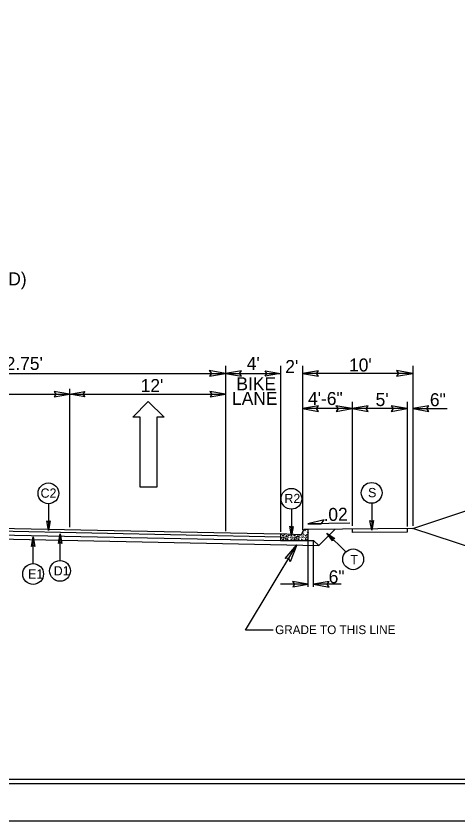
# Model space of a CAD drawing. Extents: x 957297 to 961629, y 830661 to 840840.
# Drawn here: x 959624.2 to 959889, y 837206.3 to 837689.4 of the extents above; entities that cross this region are included whole.
import ezdxf

# ---------------------------------------------------------------- set-up
doc = ezdxf.new("R2010")
doc.units = 0
for name, color, linetype in [('Old_Level_1', 7, 'Continuous'), ('Old_Level_11', 7, 'Continuous'), ('Old_Level_3', 7, 'Continuous'), ('Prop Dimension Text', 7, 'Continuous'), ('Prop Lane Arrow CELL', 7, 'Continuous'), ('Sheet Plot Border Inside CELL', 7, 'Continuous'), ('Sheet Plot Border Outside CELL', 7, 'Continuous'), ('Sheet Typical CELL', 7, 'Continuous'), ('Typical ID Circle CELL', 7, 'Continuous'), ('Typical Terminator CELL', 7, 'Continuous'), ('Typical Text ID Circle CELL', 7, 'Continuous')]:
    doc.layers.add(name, color=color, linetype=linetype)

# ---------------------------------------------------------------- blocks, each defined once
blk = doc.blocks.new('Lane Arrow Through')
at = {"layer": 'Prop Lane Arrow CELL'}
for p, q in [((-3.15, 1.6), (-3.15, 3.1)), ((-3.15, 3.1), (0, 0)), ((-17.15, 1.6), (-3.15, 1.6)), ((-17.15, -1.7), (-17.15, 1.6)), ((0, 0), (-3.15, -3.2)), ((-3.15, -1.7), (-17.15, -1.7)), ((-3.15, -3.2), (-3.15, -1.7))]:
    blk.add_line(p, q, dxfattribs=at)

msp = doc.modelspace()

# ---------------------------------------------------------------- linework, layer by layer
at = {"layer": 'Old_Level_1'}
for p, q in [((959749.66, 837479.5), (959749.66, 837380.2)), ((959782.66, 837479.5), (959782.66, 837379.7)), ((959795.87, 837479.5), (959795.87, 837380.9)), ((959861.91, 837479.5), (959861.91, 837383.36)), ((959494.54, 837474.88), (959749.66, 837474.88)), ((959749.66, 837474.88), (959782.66, 837474.88)), ((959861.91, 837474.88), (959795.87, 837474.88)), ((959562.7, 837462.34), (959656.18, 837462.34)), ((959656.18, 837465.69), (959656.18, 837382.66)), ((959656.18, 837462.34), (959749.66, 837462.34)), ((959825.59, 837457.89), (959825.59, 837383.36)), ((959858.61, 837457.89), (959858.61, 837382.99)), ((959825.59, 837453.73), (959795.87, 837453.73)), ((959858.61, 837453.73), (959825.59, 837453.73)), ((959861.91, 837453.73), (959882.58, 837453.73)), ((959861.91, 837381.88), (959939.1, 837407.61)), ((959824.16, 837385.02), (959799.05, 837384.52)), ((959562.67, 837381.32), (959782.66, 837376.87)), ((959562.7, 837383.05), (959782.66, 837378.6)), ((959861.91, 837381.88), (959798.95, 837381.25)), ((959805.6, 837371.49), (959815.53, 837381.42)), ((959825.59, 837381.52), (959825.59, 837379.34)), ((959858.61, 837381.85), (959858.61, 837379.67)), ((959939.1, 837356.15), (959861.91, 837381.88)), ((959546.62, 837376.89), (959805.61, 837371.66)), ((959562.62, 837379.07), (959782.66, 837374.62)), ((959858.61, 837379.67), (959825.59, 837379.34)), ((959761.73, 837320.85), (959792.43, 837371.92)), ((959799.24, 837374.62), (959802.54, 837374.55)), ((959799.24, 837346.72), (959799.24, 837374.34)), ((959802.54, 837374.55), (959805.6, 837371.49)), ((959802.54, 837346.72), (959802.54, 837374.34)), ((959799.24, 837348.31), (959782.64, 837348.31)), ((959819.14, 837348.31), (959802.54, 837348.31)), ((959778.35, 837320.85), (959761.73, 837320.85))]:
    msp.add_line(p, q, dxfattribs=at)
at = {"layer": 'Old_Level_11'}
for p, q in [((959808.79, 837386.93), (959799.05, 837384.52)), ((959807.06, 837384.68), (959808.79, 837386.93)), ((959799.05, 837384.52), (959807.06, 837384.68))]:
    msp.add_line(p, q, dxfattribs=at)
for points in [[(959740.05, 837473.22), (959749.66, 837474.88), (959740, 837476.59), (959741.22, 837474.88)], [(959759.27, 837476.53), (959749.66, 837474.88), (959759.33, 837473.16), (959758.1, 837474.88)], [(959805.48, 837476.53), (959795.87, 837474.88), (959805.54, 837473.16), (959804.31, 837474.88)], [(959852.3, 837473.22), (959861.91, 837474.88), (959852.25, 837476.59), (959853.47, 837474.88)], [(959805.48, 837455.38), (959795.87, 837453.73), (959805.54, 837452.01), (959804.31, 837453.73)], [(959815.98, 837452.07), (959825.59, 837453.73), (959815.93, 837455.44), (959817.15, 837453.73)], [(959835.2, 837455.38), (959825.59, 837453.73), (959835.26, 837452.01), (959834.03, 837453.73)], [(959849, 837452.07), (959858.61, 837453.73), (959848.95, 837455.44), (959850.17, 837453.73)], [(959871.52, 837455.38), (959861.91, 837453.73), (959871.58, 837452.01), (959870.35, 837453.73)], [(959785.42, 837363.81), (959792.43, 837371.92), (959788.55, 837361.85), (959787.66, 837363.97)]]:
    msp.add_lwpolyline(points, close=True, dxfattribs=at)
at = {"layer": 'Old_Level_3'}
for p, q in [((959798.95, 837381.25), (959797.57, 837381.25)), ((959799.24, 837377.93), (959799.24, 837380.97)), ((959794.2, 837378.02), (959782.66, 837378.6)), ((959782.66, 837378.6), (959782.66, 837374.62)), ((959783.92, 837377.67), (959784.5, 837377.7)), ((959784.5, 837377.12), (959783.92, 837377.67)), ((959784.13, 837375.65), (959783.95, 837375.03)), ((959784.59, 837375), (959784.13, 837375.65)), ((959784.5, 837377.7), (959784.5, 837377.12)), ((959786.18, 837377.06), (959787.02, 837377.3)), ((959786.92, 837376.81), (959786.18, 837377.06)), ((959787.02, 837377.3), (959786.92, 837376.81)), ((959790.65, 837377.67), (959791.23, 837377.7)), ((959791.23, 837377.12), (959790.65, 837377.67)), ((959790.86, 837375.65), (959790.68, 837375.03)), ((959791.32, 837375), (959790.86, 837375.65)), ((959791.23, 837377.7), (959791.23, 837377.12)), ((959792.91, 837377.06), (959793.74, 837377.3)), ((959793.65, 837376.81), (959792.91, 837377.06)), ((959793.74, 837377.3), (959793.65, 837376.81)), ((959794.2, 837378.02), (959794.2, 837378.02)), ((959795.9, 837379.06), (959795.75, 837379.09)), ((959795.79, 837379.21), (959795.9, 837379.06)), ((959797.38, 837377.67), (959797.96, 837377.7)), ((959797.96, 837377.12), (959797.38, 837377.67)), ((959797.58, 837375.65), (959797.41, 837375.03)), ((959798.05, 837375), (959797.58, 837375.65)), ((959797.96, 837377.7), (959797.96, 837377.12)), ((959799.24, 837374.62), (959799.24, 837377.93)), ((959782.66, 837374.62), (959799.24, 837374.62)), ((959783.95, 837375.03), (959784.59, 837375)), ((959786.86, 837375.34), (959786.3, 837374.94)), ((959786.3, 837374.94), (959787.2, 837374.73)), ((959787.2, 837374.73), (959786.86, 837375.34)), ((959790.68, 837375.03), (959791.32, 837375)), ((959793.59, 837375.34), (959793.03, 837374.94)), ((959793.03, 837374.94), (959793.93, 837374.73)), ((959793.93, 837374.73), (959793.59, 837375.34)), ((959797.41, 837375.03), (959798.05, 837375))]:
    msp.add_line(p, q, dxfattribs=at)
for centre in [(959796.3, 837380.41), (959797.4, 837380.53), (959798.26, 837380.16), (959782.87, 837377.21), (959783.15, 837378.32), (959783.21, 837375.74), (959783.36, 837376.29), (959784.16, 837376.63), (959784.41, 837376.08), (959784.93, 837376.53), (959785.08, 837378.13), (959785.52, 837375.86), (959785.63, 837376.93), (959785.81, 837376.05), (959785.91, 837375.53), (959786.34, 837377.52), (959786.86, 837376.05), (959787.51, 837376.32), (959787.78, 837377.67), (959788.46, 837375.43), (959788.86, 837377.27), (959788.89, 837376.47), (959788.98, 837376.2), (959789.6, 837377.21), (959789.94, 837375.74), (959790.09, 837376.29), (959790.89, 837376.63), (959791.14, 837376.08), (959791.66, 837376.53), (959792.24, 837375.86), (959792.36, 837376.93), (959792.54, 837376.05), (959792.63, 837375.53), (959793.07, 837377.52), (959793.59, 837376.05), (959794.23, 837376.32), (959794.51, 837377.67), (959795.19, 837375.43), (959795.5, 837378.29), (959795.59, 837377.27), (959795.62, 837376.47), (959795.71, 837376.2), (959796.26, 837379.12), (959796.33, 837377.21), (959796.6, 837378.32), (959796.66, 837375.74), (959796.82, 837376.29), (959797.25, 837379.61), (959797.62, 837376.63), (959797.86, 837376.08), (959798.39, 837376.53), (959798.42, 837379.43), (959798.54, 837378.13), (959798.97, 837375.86), (959799.09, 837376.93), (959799.18, 837379.52), (959785.08, 837375), (959785.6, 837374.76), (959789.14, 837375.28), (959791.81, 837375), (959792.33, 837374.76), (959795.86, 837375.28), (959798.54, 837375), (959799.06, 837374.76)]:
    msp.add_circle(centre, 0.0432, dxfattribs=at)
for centre, radius, start, end in [((959797.58, 837379.6), 1.66, 90, 178.9266), ((959798.95, 837380.97), 0.287, 0, 90), ((959799.06, 837381.18), 0.0432, 169.6531, 280.3469), ((959788.77, 837378.29), 0.0432, 164.1199, 10.1626), ((959791.81, 837378.13), 0.0432, 162.062, 12.2205), ((959794.28, 837379.66), 1.64, 267.1376, 358.9266), ((959799.27, 837376.05), 0.0432, 150.4173, 209.5827)]:
    msp.add_arc(centre, radius, start, end, dxfattribs=at)
at = {"layer": 'Sheet Plot Border Inside CELL'}
msp.add_lwpolyline([(960390.3, 838283.82), (958723.8, 838283.82), (958723.8, 837228.72), (960390.3, 837228.72)], close=True, dxfattribs=at)
at = {"layer": 'Sheet Plot Border Outside CELL'}
msp.add_lwpolyline([(960394.8, 838306.27), (958710.8, 838306.27), (958710.8, 837206.27), (960394.8, 837206.27)], close=True, dxfattribs=at)
at = {"layer": 'Sheet Typical CELL'}
msp.add_lwpolyline([(960377.8, 838281.27), (958877.8, 838281.27), (958877.8, 837231.27), (960377.8, 837231.27)], close=True, dxfattribs=at)
at = {"layer": 'Typical ID Circle CELL'}
for p, q in [((959643.55, 837396.67), (959643.55, 837380.58)), ((959837.33, 837396.97), (959837.33, 837380.88)), ((959789.22, 837393.42), (959789.22, 837377.33)), ((959634.38, 837360.7), (959634.38, 837376.79)), ((959650.51, 837362.56), (959650.51, 837378.65)), ((959821.83, 837367.71), (959810.46, 837379.09))]:
    msp.add_line(p, q, dxfattribs=at)
for centre in [(959837.33, 837403.19), (959643.55, 837402.89), (959789.22, 837399.64), (959826.23, 837363.31), (959650.51, 837356.34), (959634.38, 837354.48)]:
    msp.add_circle(centre, 6.23, dxfattribs=at)
at = {"layer": 'Typical Terminator CELL'}
for points in [[(959773.44, 837476.47), (959782.66, 837474.88), (959773.39, 837473.24), (959774.57, 837474.88)], [(959646.96, 837460.75), (959656.18, 837462.34), (959646.91, 837463.98), (959648.09, 837462.34)], [(959665.4, 837460.75), (959656.18, 837462.34), (959665.46, 837463.98), (959664.28, 837462.34)], [(959740.44, 837460.75), (959749.66, 837462.34), (959740.39, 837463.98), (959741.57, 837462.34)], [(959644.54, 837386.35), (959643.55, 837380.58), (959642.52, 837386.38), (959643.55, 837385.64)], [(959838.33, 837386.65), (959837.33, 837380.88), (959836.31, 837386.68), (959837.33, 837385.94)], [(959790.22, 837383.09), (959789.22, 837377.33), (959788.2, 837383.13), (959789.22, 837382.39)], [(959633.39, 837371.02), (959634.38, 837376.79), (959635.4, 837370.99), (959634.38, 837371.73)], [(959649.52, 837372.89), (959650.51, 837378.65), (959651.54, 837372.85), (959650.51, 837373.59)], [(959813.83, 837374.31), (959810.46, 837379.09), (959815.28, 837375.71), (959814.03, 837375.51)], [(959790.01, 837346.72), (959799.24, 837348.31), (959789.96, 837349.94), (959791.14, 837348.31)], [(959811.76, 837349.89), (959802.54, 837348.31), (959811.81, 837346.67), (959810.63, 837348.31)]]:
    msp.add_lwpolyline(points, close=True, dxfattribs=at)

# ---------------------------------------------------------------- block references
at = {"layer": 'Old_Level_1', "xscale": 3, "yscale": 3, "rotation": 90}
msp.add_blockref('Lane Arrow Through', (959703.41, 837458.03), dxfattribs=at)

# ---------------------------------------------------------------- texts
at = {"layer": 'Old_Level_1'}
msp.add_text('GRADE TO THIS LINE', height=5.2473, dxfattribs=at).set_placement((959779.48, 837318.4))
at = {"layer": 'Old_Level_3'}
for s, p in [("4'", (959762.46, 837477.01)), ("2'", (959785.53, 837475.12)), ("10'", (959823.77, 837476.05)), ('BIKE', (959756.22, 837464.77)), ('LANE', (959753.64, 837456.02)), ('4\'-6"', (959799.18, 837455.92)), ("5'", (959839.68, 837455.29)), ('6"', (959872.23, 837455.2))]:
    msp.add_text(s, height=7.801, dxfattribs=at).set_placement(p)
at = {"layer": 'Prop Dimension Text'}
for s, height, rotation, p in [('-L- NC 8 (WINSTON ROAD)', 7.7675, 0, (959499.5, 837527.77)), ("32.75'", 7.801, 0, (959612.12, 837476.95)), ("12'", 7.801, 0, (959698.86, 837463.72)), ('.02', 7.801, 1.1839, (959808.54, 837386.22)), ('6"', 7.801, 0, (959811.56, 837348.91))]:
    msp.add_text(s, height=height, rotation=rotation, dxfattribs=at).set_placement(p)
at = {"layer": 'Typical Text ID Circle CELL'}
for s, height, p in [('C2', 5.572, (959638.84, 837400.26)), ('S', 5.57, (959835.16, 837400.56)), ('R2', 5.572, (959785.03, 837397.01)), ('T', 5.57, (959824.53, 837360.33)), ('E1', 5.572, (959631.35, 837351.74)), ('D1', 5.572, (959646.72, 837353.6))]:
    msp.add_text(s, height=height, dxfattribs=at).set_placement(p)

doc.saveas('drawing.dxf')
